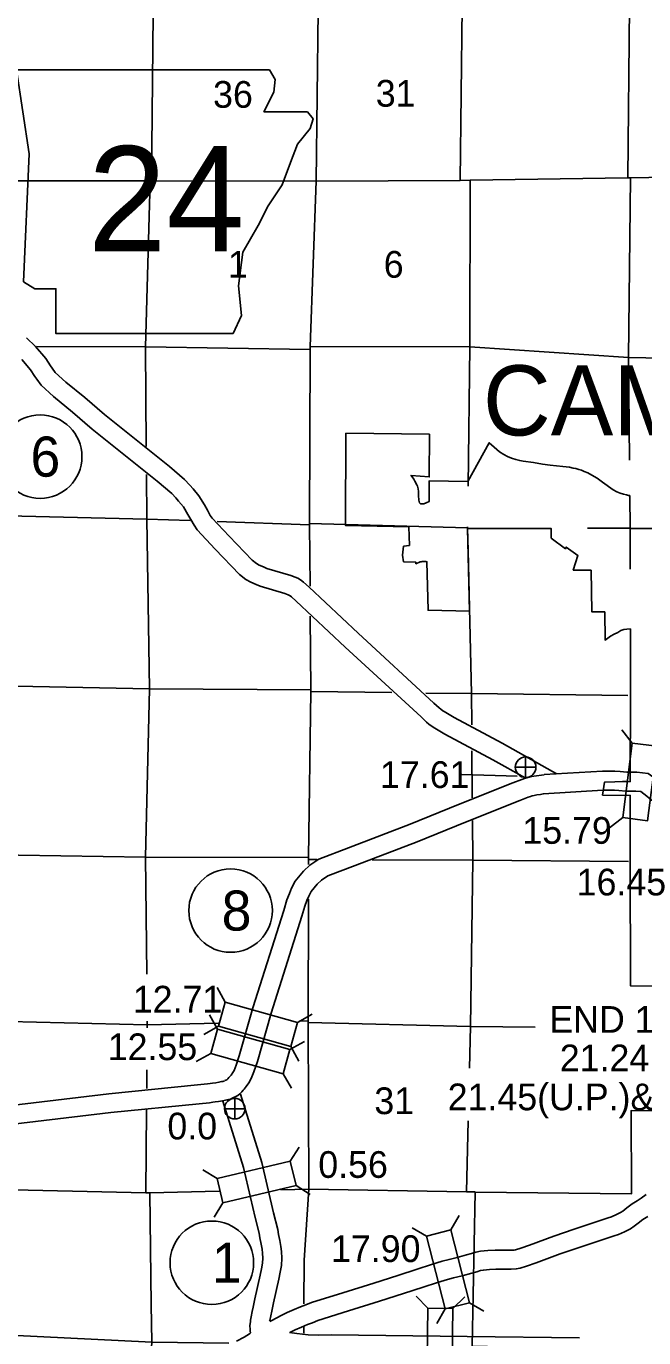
# Model space of a CAD drawing. Extents: x 369523 to 838377, y 495025 to 936819.
# Drawn here: x 630067 to 649583, y 566136 to 607625 of the extents above; entities that cross this region are included whole.
import ezdxf

# ---------------------------------------------------------------- set-up
doc = ezdxf.new("R2010")
doc.units = 0
for name, color, linetype in [('22', 7, 'Continuous'), ('DSN_BRDG_Annotation', 7, 'Continuous'), ('DSN_DRFT_Common-Annotations', 7, 'Continuous'), ('DSN_DRFT_Common-Line', 7, 'Continuous'), ('DSN_DRFT_Junk-No-Plot', 7, 'Continuous'), ('Level 1', 7, 'Continuous'), ('Level 11', 7, 'Continuous'), ('Level 15', 7, 'Continuous'), ('Level 2', 7, 'Continuous'), ('Level 21', 7, 'Continuous'), ('Level 22', 7, 'Continuous')]:
    doc.layers.add(name, color=color, linetype=linetype)

msp = doc.modelspace()

# ---------------------------------------------------------------- linework, layer by layer
at = {"layer": '22'}
msp.add_lwpolyline([(629763, 606250), (630162, 603586), (629985, 599544), (630340, 599322), (631006, 599322), (631006, 597901), (636602, 597901), (636868, 598479), (636779, 599411), (636913, 600477), (637401, 601321), (637712, 601943), (638156, 602609), (638423, 603319), (638645, 603897), (639044, 604385), (639133, 604696), (638955, 604918), (637579, 604918), (637890, 605540), (637934, 605939), (637750, 606246)], close=True, dxfattribs=at)
at = {"layer": 'DSN_BRDG_Annotation'}
msp.add_line((643833, 583952), (645586, 583906), dxfattribs=at)
at = {"layer": 'DSN_DRFT_Common-Annotations'}
for p, q in [((645524, 584184), (646174, 584184)), ((645849, 583859), (645849, 584509)), ((636332, 573382), (636982, 573382)), ((636657, 573057), (636657, 573707))]:
    msp.add_line(p, q, dxfattribs=at)
for centre in [(645849, 584184), (636657, 573382)]:
    msp.add_circle(centre, 325, dxfattribs=at)
at = {"layer": 'DSN_DRFT_Common-Line'}
for centre in [(630508, 594010), (636525, 579650), (635933, 568508)]:
    msp.add_circle(centre, 1320, dxfattribs=at)
at = {"layer": 'Level 1'}
for points in [[(646841, 583979), (646838, 583979), (646789, 583999), (646694, 584052), (645104, 584945), (643591, 585757), (643326, 585916), (643276, 585942), (643231, 585969), (643165, 586018), (643116, 586060), (642951, 586213), (640554, 588426), (639009, 589875), (638828, 590043), (638735, 590110), (638649, 590160), (638561, 590196), (638427, 590245), (637671, 590475), (637570, 590521), (637425, 590580), (637343, 590626), (637208, 590730), (636476, 591492), (635943, 592063), (635885, 592152), (635792, 592314), (635696, 592482), (635525, 592766), (635341, 592987), (635241, 593109), (635073, 593282), (634592, 593693), (632536, 595342), (631921, 595877), (631321, 596370), (630983, 596674), (630889, 596805), (630834, 596883), (630683, 597112), (630361, 597493), (630072, 597766)], [(645840, 583844), (644816, 584419), (643294, 585235), (643034, 585392), (642985, 585417), (642898, 585469), (642791, 585548), (642716, 585613), (642543, 585773), (640145, 587986), (638599, 589437), (638447, 589578), (638407, 589607), (638385, 589620), (638345, 589636), (638235, 589676), (637460, 589912), (637333, 589969), (637163, 590039), (637012, 590124), (636806, 590282), (636040, 591079), (635468, 591692), (635373, 591839), (635272, 592016), (635179, 592178), (635035, 592417), (634878, 592605), (634792, 592710), (634663, 592844), (634209, 593230), (632151, 594882), (631534, 595419), (630930, 595915), (630534, 596270), (630399, 596458), (630337, 596546), (630202, 596752), (629925, 597080)], [(636836, 573845), (637509, 571685), (637886, 570083), (638016, 569565), (638040, 569404), (638082, 569212), (638116, 569027), (638135, 568862), (638143, 568649), (638129, 568425), (638095, 568213), (638053, 567989), (637882, 567240), (637829, 566974), (637796, 566834), (637763, 566677), (637759, 566659)], [(636276, 573624), (636929, 571527), (637303, 569941), (637427, 569448), (637449, 569296), (637493, 569094), (637522, 568938), (637536, 568815), (637542, 568657), (637532, 568492), (637504, 568315), (637465, 568111), (637295, 567365), (637243, 567102), (637211, 566966), (637174, 566794), (637155, 566692), (637151, 566642), (637144, 566588), (637135, 566512), (637141, 566406), (637145, 566342), (637156, 566293)], [(638392, 566298), (638615, 566266), (638972, 566225), (639318, 566214), (639712, 566224), (644006, 566172), (647548, 566136)]]:
    msp.add_lwpolyline(points, dxfattribs=at)
at = {"layer": 'Level 11'}
for points in [[(636348, 574272), (636404, 574298), (636417, 574305), (636437, 574326), (636473, 574367), (636496, 574392), (636539, 574447), (636595, 574523), (636634, 574592), (636700, 574757), (636801, 575055), (637229, 576576), (638203, 579655), (638305, 579987), (638382, 580187), (638451, 580356), (638566, 580583), (638826, 580899), (639028, 581083), (639314, 581280), (640251, 581638), (642202, 582380), (643723, 583004), (645448, 583690), (645725, 583799), (645819, 583832), (645893, 583853), (645992, 583880), (646112, 583900), (646432, 583947)], [(646435, 583949), (648275, 584060), (648672, 584055), (648833, 584051), (649046, 584030), (649184, 584029), (649369, 584032), (649720, 583988), (650056, 583743), (650154, 583659), (650217, 583632), (650421, 583531), (650552, 583470), (650676, 583419), (650762, 583379), (650876, 583334), (650988, 583275), (651068, 583215), (651116, 583178), (651220, 583107), (651370, 582954), (651588, 582701), (652619, 581412), (653171, 580721)], [(636599, 573727), (636666, 573758), (636749, 573800), (636815, 573852), (636879, 573920), (636918, 573964), (636954, 574003), (637018, 574085), (637101, 574198), (637176, 574333), (637263, 574549), (637374, 574878), (637804, 576404), (638775, 579476), (638872, 579790), (638940, 579967), (638997, 580107), (639071, 580253), (639262, 580485), (639402, 580612), (639596, 580745), (640465, 581077), (642422, 581822), (643948, 582447), (645669, 583132), (645933, 583236), (646002, 583260), (646056, 583276), (646121, 583293), (646204, 583307), (646315, 583324), (646409, 583346)], [(646411, 583347), (648289, 583460), (648662, 583455), (648796, 583452), (649014, 583430), (649187, 583429), (649337, 583431), (649492, 583412), (649684, 583272), (649832, 583146), (649963, 583088), (650162, 582990), (650312, 582920), (650435, 582869), (650524, 582828), (650625, 582788), (650668, 582765), (650707, 582736), (650766, 582692), (650833, 582646), (650928, 582548), (651126, 582318), (652150, 581037), (652672, 580384)], [(629587, 573487), (632678, 573856), (635476, 574138), (635793, 574167), (635878, 574179), (635954, 574189), (636055, 574204), (636157, 574221), (636242, 574238), (636279, 574246), (636313, 574254), (636333, 574265)], [(629651, 572890), (632743, 573260), (635534, 573540), (635862, 573571), (635961, 573585), (636037, 573595), (636147, 573611), (636268, 573631), (636362, 573650), (636409, 573660), (636465, 573674), (636526, 573688), (636614, 573734)], [(649658, 570673), (649499, 570555), (649376, 570469), (649221, 570368), (649046, 570244), (648919, 570145), (648851, 570098), (648722, 570031), (648567, 569965), (648457, 569928), (647386, 569571)], [(649712, 569972), (649559, 569872), (649404, 569762), (649275, 569662), (649162, 569583), (648978, 569488), (648781, 569404), (648647, 569359), (647575, 569002)], [(637766, 566650), (637829, 566686), (638128, 566844), (638316, 566931), (638532, 567027), (638731, 567112), (638901, 567175), (639087, 567247), (640076, 567556), (641051, 567865), (641812, 568104), (642425, 568305), (642877, 568453), (643212, 568558), (643428, 568614), (643691, 568679), (643985, 568758), (644139, 568802), (644280, 568843), (644428, 568871), (644657, 568894), (644885, 568907), (645184, 568909), (645383, 568906), (645489, 568910), (645528, 568917), (645693, 568968), (645976, 569067), (646741, 569351), (647383, 569571)], [(638391, 566304), (638395, 566306), (638564, 566385), (638771, 566476), (638953, 566554), (639113, 566613), (639285, 566680), (640256, 566984), (641231, 567293), (641995, 567532), (642612, 567735), (643060, 567882), (643377, 567981), (643575, 568032), (643842, 568099), (644145, 568180), (644305, 568226), (644419, 568259), (644514, 568277), (644704, 568296), (644903, 568307), (645182, 568309), (645390, 568306), (645555, 568312), (645672, 568334), (645881, 568398), (646179, 568503), (646942, 568786), (647578, 569003)], [(636711, 566025), (636957, 566158), (637128, 566259), (637159, 566282)]]:
    msp.add_lwpolyline(points, dxfattribs=at)
at = {"layer": 'Level 15'}
for points in [[(639045, 597495), (639229, 602722), (639296, 608126), (639302, 608196), (639217, 613566), (639217, 613634), (639248, 618581), (639249, 618617), (639316, 623803), (639307, 629047), (639321, 631663)], [(644096, 602751), (649078, 602825), (649164, 602830), (654375, 602924), (654499, 602927), (656145, 602956)], [(620951, 602835), (623474, 602825), (623538, 602833), (628703, 602739), (628737, 602738), (633985, 602731), (634029, 602734), (639229, 602722), (643785, 602748), (644096, 602751)], [(639022, 591892), (639040, 597399), (639045, 597495)], [(639036, 589909), (639021, 591854), (639022, 591892)], [(638990, 581110), (638991, 581264), (638986, 581332), (639059, 586576), (639063, 586637), (639044, 588967)], [(638841, 567204), (638847, 568588), (638997, 570834), (638981, 576112), (638980, 576158), (638988, 580014)], [(619613, 570993), (623306, 570881), (623381, 570885), (628639, 570833), (628725, 570835), (633842, 570720), (633972, 570721), (636159, 570770)], [(638110, 570814), (638997, 570834), (643986, 570749), (644254, 570751)], [(638837, 566279), (638838, 566485)]]:
    msp.add_lwpolyline(points, dxfattribs=at)
at = {"layer": 'Level 2'}
for points in [[(642161, 591785), (640156, 591834), (640171, 594750), (642811, 594720), (642804, 593368), (642227, 593414), (642312, 593292), (642345, 593233), (642411, 593117), (642434, 593070), (642452, 592993), (642460, 592903), (642465, 592785), (642477, 592629), (642497, 592551), (642525, 592521), (642547, 592514), (642580, 592511), (642628, 592521), (642705, 592544), (642800, 592589), (642804, 593245), (644026, 593223)], [(644026, 593223), (644698, 594448), (644851, 594305), (645029, 594163), (645158, 594075), (645273, 594013), (645401, 593960), (645544, 593919), (645666, 593887), (645774, 593863), (646094, 593821), (646387, 593776), (646628, 593744), (647027, 593696), (647233, 593671)], [(647233, 593671), (647354, 593647), (647441, 593630), (647535, 593602), (647619, 593581), (647703, 593542), (647814, 593494), (647943, 593424), (648106, 593323), (648284, 593201), (648618, 592961), (648736, 592894), (648841, 592849), (648942, 592818), (649036, 592797), (649097, 592785), (649144, 592779)], [(649144, 592779), (649154, 591737), (651811, 591731), (651816, 590411), (652806, 590411)], [(644011, 591739), (644075, 589120), (642766, 589148), (642729, 590685), (642696, 590689), (642661, 590691), (642614, 590691), (642579, 590689), (642552, 590685), (642521, 590679), (642476, 590664), (642418, 590639), (642396, 590628), (642381, 590620), (642381, 590668), (641991, 590682), (641962, 590889), (641992, 591174), (642175, 591199), (642161, 591785)], [(647925, 590418), (647357, 590419), (647503, 590886), (647135, 591146), (647109, 591098), (646654, 591433), (646652, 591738), (644011, 591739)], [(649158, 583727), (649163, 586446), (649159, 588561), (649052, 588556), (648956, 588540), (648863, 588509), (648760, 588447), (648646, 588390), (648535, 588325), (648360, 588207), (648348, 589096), (647946, 589098), (647925, 590418)], [(651832, 573280), (651830, 575928), (651827, 577241), (649167, 577266), (649154, 581204), (649157, 583290), (648280, 583301), (648343, 583712), (648671, 583720), (648908, 583730), (649044, 583731), (649158, 583727)], [(644256, 570745), (649197, 570694), (649184, 573324), (651832, 573280)], [(649517, 565751), (644165, 565871), (644256, 570745)]]:
    msp.add_lwpolyline(points, dxfattribs=at)
at = {"layer": 'Level 21'}
for p, q in [((649216, 584946), (648892, 585363)), ((648919, 582589), (648501, 582265)), ((636357, 576755), (636098, 577216)), ((636114, 575894), (635856, 576354)), ((638644, 576111), (639104, 576370)), ((636142, 575993), (635681, 575734)), ((638401, 575250), (638862, 575508)), ((635900, 575131), (635439, 574873)), ((638429, 575349), (638687, 574888)), ((638187, 574487), (638445, 574027)), ((638413, 571719), (638691, 572168)), ((636100, 571174), (635651, 571452)), ((638594, 570948), (639043, 570670)), ((636282, 570403), (636004, 569954)), ((643484, 569545), (643752, 570000)), ((642717, 569348), (642262, 569616)), ((642755, 567075), (642387, 567453)), ((643547, 567065), (643925, 567434)), ((644077, 567245), (644532, 566977)), ((643311, 567047), (643042, 566592))]:
    msp.add_line(p, q, dxfattribs=at)
for points in [[(649216, 584946), (648919, 582589), (649704, 582490), (650002, 584847)], [(636142, 575993), (638429, 575349), (638644, 576111), (636357, 576755)], [(638401, 575250), (636114, 575894), (635900, 575131), (638187, 574487)], [(636282, 570403), (638594, 570948), (638413, 571719), (636100, 571174)], [(644077, 567245), (643484, 569545), (642717, 569348), (643311, 567047)], [(642755, 567075), (642726, 564699), (643518, 564689), (643547, 567065)]]:
    msp.add_lwpolyline(points, close=True, dxfattribs=at)
at = {"layer": 'Level 22'}
for points in [[(634093, 634475), (634036, 629194), (634069, 623934), (634032, 618609), (634099, 613403), (634077, 608018), (634029, 602734)], [(643785, 602748), (643844, 608230), (643888, 613629), (643762, 618692), (643769, 618899)], [(649150, 608800), (649133, 608249), (649078, 602825)], [(633836, 597479), (633985, 602731)], [(644088, 597483), (644096, 602751)], [(649164, 602830), (649101, 597143), (649132, 593898)], [(639040, 597399), (633836, 597479), (630398, 597497)], [(633860, 594335), (633836, 597479)], [(644088, 597483), (639045, 597495)], [(644031, 593073), (644088, 597483)], [(657982, 597015), (654585, 597036), (649101, 597143), (644088, 597483)], [(633876, 577638), (633838, 581335), (633967, 586660), (633877, 592031), (633867, 593445)], [(607584, 592340), (612877, 592302), (618145, 592274), (623315, 592193), (628599, 592161), (633877, 592031), (635243, 591984)], [(636099, 591955), (639021, 591854)], [(639022, 591892), (644014, 591752)], [(644031, 591037), (644014, 591752), (644014, 591792)], [(647807, 591751), (649153, 591751), (654474, 591705), (658833, 591733)], [(649151, 591920), (649153, 591751), (649151, 590452)], [(644145, 585527), (644136, 586513), (644031, 591037)], [(607544, 587007), (612836, 586984), (618058, 586891), (623263, 586825), (628684, 586774), (633967, 586660), (639063, 586637)], [(639059, 586576), (641620, 586544)], [(642698, 586531), (644136, 586513)], [(644136, 586513), (649079, 586453)], [(644165, 583215), (644152, 584705)], [(644075, 574663), (644106, 575984), (644183, 581239), (644172, 582497)], [(638986, 581332), (633838, 581335), (628472, 581424), (623224, 581494), (617925, 581662), (612786, 581761), (607513, 581658)], [(638991, 581264), (639257, 581263)], [(641004, 581254), (644183, 581239)], [(649102, 581199), (644183, 581239)], [(616874, 576342), (618124, 576314), (623296, 576251), (628636, 576157), (633893, 576039), (636141, 576091)], [(633892, 575944), (633893, 576039), (633892, 576149)], [(638691, 576151), (638980, 576158)], [(638981, 576112), (644106, 575984)], [(644106, 575984), (646154, 575963)], [(633874, 574022), (633879, 574608)], [(633842, 570720), (633867, 573354)], [(643986, 570749), (644038, 572998)], [(634016, 567187), (633972, 570721)], [(633925, 564172), (634031, 565992), (634016, 567187)], [(617882, 566348), (623296, 566251), (628697, 566257), (634031, 565992), (636471, 565960)]]:
    msp.add_lwpolyline(points, dxfattribs=at)

# ---------------------------------------------------------------- texts
at = {"layer": '22'}
msp.add_text('24', height=3326.4, dxfattribs=at).set_placement((632019, 600506))
at = {"layer": 'DSN_BRDG_Annotation'}
for s, p in [('17.61', (641247, 583528)), ('END 17.98', (646598, 575784)), ('21.45(U.P.)&END', (643387, 573333)), ('0.0', (634527, 572410))]:
    msp.add_text(s, height=844.8, dxfattribs=at).set_placement(p)
at = {"layer": 'DSN_DRFT_Common-Annotations'}
msp.add_text('CAMDEN', height=2217.6, dxfattribs=at).set_placement((644502, 594680))
at = {"layer": 'DSN_DRFT_Common-Line'}
for s, p in [('6', (630201, 593376)), ('8', (636242, 579016)), ('1', (635933, 567875))]:
    msp.add_text(s, height=1267, dxfattribs=at).set_placement(p)
at = {"layer": 'DSN_DRFT_Junk-No-Plot'}
for s, p in [('15.79', (645747, 581762)), ('16.45', (647463, 580129)), ('12.71', (633435, 576424)), ('12.55', (632643, 574918)), ('21.24 BR.', (646930, 574566)), ('0.56', (639297, 571194)), ('17.90', (639700, 568532))]:
    msp.add_text(s, height=844.8, dxfattribs=at).set_placement(p)
at = {"layer": 'Level 22'}
for s, height, p in [('36', 844.8, (635972, 605046)), ('31', 844.8, (641114, 605080)), ('1', 845, (636440, 599670)), ('6', 845, (641365, 599670)), ('31', 844.8, (641068, 573210))]:
    msp.add_text(s, height=height, dxfattribs=at).set_placement(p)

doc.saveas('drawing.dxf')
